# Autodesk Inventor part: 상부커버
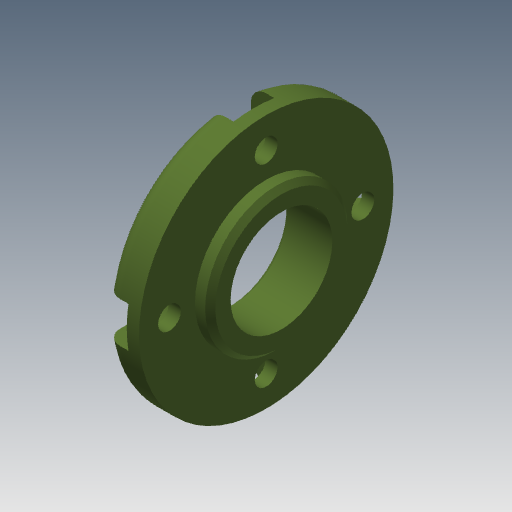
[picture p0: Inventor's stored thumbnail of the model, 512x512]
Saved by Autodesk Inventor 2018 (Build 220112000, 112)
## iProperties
Created: 2019-01
Part Number: 상부커버
Material: 알루미늄 6061
Document SubType Name: Modeling
Designer: mduedu
Density: 2.71 g/cm^3
Appearance: 올리브 녹색
Mass: 28.8859 g
Surface Area: 53.2237 cm^2
Volume: 10.659 cm^3
Author: mduedu
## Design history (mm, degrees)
sketch "스케치1"
  geometry: L1 (0, 0)-(7, 0); L2 (7, 0)-(7, 25); L3 (7, 25)-(0, 25); L4 (0, 25)-(0, 0); L5 (7, 0)-(10, 0); L6 (10, 0)-(10, 14); L7 (10, 14)-(7, 14); L8 (7, 14)-(7, 0)
  constraints: 16 end point, 4 parallel, 2 horizontal, 2 perpendicular
  dimensions: "d0" = 50 diameter of L3 L1; "d2" = 10 distance between parallel lines of L6 L4; "d3" = 7 distance of L2.end L3.end; "d4" = 28 diameter of L7 L5
revolve "회전1" sketch "스케치1" stored, may be unused: angle "d5" = 90 deg
sketch "스케치2"
  geometry: C1 r 10 at (0, 0); 1 further point
  constraints: 1 centre point, 1 coincident
  dimensions: "d6" = 20 diameter of C1
extrude "돌출1" cut sketch "스케치2" extent not by distance; stored distance "d7" = 10; taper "d8" = 0 deg
chamfer "모따기1" distance "d9" = 1; stored, may be unused: second distance "d10" = 2, angle "d11" = 45 deg
fillet "모깎기1" dims "d12" = 3
sketch "스케치3" dims "d13" = 38
  geometry: 6 further points
  constraints: 2 vertical alignment, 1 coincident, 7 other
  dimensions: "d16" = 360 deg dimension on point (0, 0) point (0, 19) (derived)
chamfer "모따기2" distance "d18" = 1; stored, may be unused: second distance "d19" = 2, angle "d20" = 45 deg
sketch "스케치4"
  geometry: 4 further points
  constraints: 4 other
hole "구멍1" sketch "스케치4" at (-19, 0), (0, -19), (19, 0), (0, 19) diameter "d21" = 4.5; stored, may be unused: countersink angle "d25" = 90 deg, drill point angle "d27" = 0 deg; dims "d22" = 6, "d23" = 8, "d24" = 4.6, "d26" = 8
sketch "스케치5"
  geometry: L1 (-4, 0)-(-4, 5.678); L2 (4, 0)-(4, 5.678); A1 r 4 centre (0, 0) between (-2.841, 2.816) and (2.841, 2.816) reference; A2 r 25 centre (0, -19) between (-4, 5.678) and (4, 5.678) reference; A3 r 4 centre (0, 0) between (-4, 0) and (4, 0); A4 r 25 centre (0, -19) between (4, 5.678) and (-4, 5.678); A5 r 4 centre (0, 0) between (4, 0) and (-4, 0); 1 further point
  constraints: 10 point on circle, 4 end point, 3 centre point, 2 coincident, 2 tangent, 1 parallel, 1 vertical
extrude "돌출2" cut sketch "스케치5" extent not by distance; stored distance "d28" = 10; taper "d29" = 0 deg
node "솔리드1"
pattern_circular "원형 패턴1" dims angle "d31" = 360 deg
